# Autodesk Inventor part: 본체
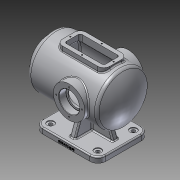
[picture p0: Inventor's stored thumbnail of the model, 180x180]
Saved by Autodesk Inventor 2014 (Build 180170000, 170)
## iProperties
Created: 2021-11
Part Number: 본체
Material: 알루미늄 6061
Document SubType Name: Modeling
Designer: kb542-04
Density: 2.71 g/cm^3
Appearance: 알루미늄 - 평지
Mass: 3554.85 g
Surface Area: 2408.31 cm^2
Volume: 1311.75 cm^3
Author: kb542-04
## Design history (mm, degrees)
sketch "스케치1"
  geometry: L1 (0, 0)-(210, 0); L2 (0, 32.5)-(25, 32.5); L3 (25, 32.5)-(25, 55); L4 (25, 55)-(181.239, 55); L5 (0, 32.5)-(0, 47.5); L6 (0, 47.5)-(10, 47.5); L7 (10, 47.5)-(10, 65); L8 (10, 65)-(181.239, 65); L9 (0, 101.95)-(170, 101.95); L10 (210, 0)-(210, 59.358); A1 r 100 centre (110, 0) between (210, 0) and (189.154, 61.111); A2 r 90 centre (110, 0) between (200, 0) and (181.239, 55); A3 r 10 centre (181.239, 55) between (189.154, 61.111) and (181.239, 65); 1 further point
  constraints: 20 end point, 7 point on circle, 5 parallel, 4 perpendicular, 3 centre point, 3 tangent, 2 point on line, 2 vertical alignment, 1 concentric, 1 horizontal
  dimensions: "d1" = 210 distance of L1.start L1.end; "d2" = 10 radial gap between concentric circles of A1 A2; "d3" = 25 distance of L2.start L2.end; "d4" = 65 diameter of L2 L1; "d5" = 95 diameter of L6 L1; "d6" = 130 diameter of L8 L1; "d7" = 10 distance between parallel lines of L7 L5; "d8" = 110 diameter of L4 L1; "d30" = 100 radius of A1; "d31" = 170 distance of L9.start L9.end; "d32" = 10 radius of A3
revolve "회전1" sketch "스케치1" stored, may be unused: angle "d10" = 90 deg
node "작업 평면1"
sketch "스케치2"
  geometry: L1 (50, -30)-(170, -30); L2 (170, -30)-(170, 30); L3 (170, 30)-(50, 30); L4 (50, 30)-(50, -30); L5 (60, -20)-(160, -20); L6 (160, -20)-(160, 20); L7 (160, 20)-(60, 20); L8 (60, 20)-(60, -20); 2 further points
  constraints: 16 end point, 4 parallel, 2 horizontal, 2 perpendicular, 1 horizontal alignment, 1 midpoint
  dimensions: "d12" = 120 distance of L2.end L3.end; "d13" = 10 distance between parallel lines of L7 L3; "d14" = 10 distance between parallel lines of L2 L6; "d15" = 10 distance between parallel lines of L4 L8; "d16" = 10 distance between parallel lines of L1 L5; "d17" = 50 distance from line of L4 point (0, 0); "d18" = 60 distance of L3.end L1.start
extrude "돌출1" join sketch "스케치2" stored distance "d19" = 10; taper "d20" = 0 deg
sketch "스케치3"
  geometry: L1 (170, 30)-(50, 30) reference; L2 (50, 30)-(50, -30) reference; L3 (50, -30)-(170, -30) reference; L4 (170, -30)-(170, 30) reference; L5 (55, 25)-(165, 25); L6 (165, 25)-(165, -25); L7 (165, -25)-(55, -25); L8 (55, -25)-(55, 25); 5 further points
  constraints: 8 end point, 4 midpoint, 3 other
  dimensions: "d21" = 50 distance of L7.end L5.start; "d22" = 55 horizontal distance of point (110, 25) point (55, 0) (derived)
hole "구멍1" sketch "스케치3" at (110, 25), (55, 0), (165, 0), (110, -25) diameter "d23" = 3.242; stored, may be unused: countersink angle "d27" = 90 deg, drill point angle "d29" = 118 deg; dims "d24" = 9, "d25" = 4, "d26" = 2, "d28" = 11
node "작업 평면2"
sketch "스케치4"
  geometry: L1 (30, 65)-(190, 65); L2 (190, 65)-(190, -65); L3 (190, -65)-(30, -65); L4 (30, -65)-(30, 65); L5 (0, -47.5)-(0, 47.5) reference; 2 further points
  constraints: 8 end point, 2 parallel, 1 horizontal, 1 horizontal alignment, 1 midpoint, 1 perpendicular
  dimensions: "d34" = 160 distance of L1.start L1.end; "d35" = 130 distance of L3.end L1.start; "d36" = 30 distance between parallel lines of L4 L5
extrude "돌출2" join sketch "스케치4" distance "d37" = 14; taper "d38" = 0 deg
fillet "모깎기1" dims "d39" = 20
sketch "스케치5"
  geometry: L1 (170, 7)-(170, -7); L2 (50, -7)-(50, 7); L3 (103, 50)-(117, 50); L4 (117, -50)-(103, -50); L5 (50, 7)-(103, 7); L6 (117, 7)-(170, 7); L7 (103, -50)-(103, -7); L8 (103, 7)-(103, 50); L9 (170, -7)-(117, -7); L10 (103, -7)-(50, -7); L11 (117, 50)-(117, 7); L12 (117, -7)-(117, -50); L13 (30, -45)-(30, 45) reference; 2 further points
  constraints: 24 end point, 10 parallel, 6 collinear, 4 perpendicular, 3 horizontal, 1 horizontal alignment, 1 midpoint
  dimensions: "d40" = 14 distance of L3.start L3.end; "d41" = 14 distance of L1.start L1.end; "d42" = 73 distance between parallel lines of L8 L13; "d43" = 120 distance between parallel lines of L1 L2; "d44" = 100 distance between parallel lines of L3 L4
extrude "돌출3" join sketch "스케치5" stored distance "d45" = 14; taper "d46" = 0 deg
feature "면 기울기1" dims angle "d47" = 20 deg
feature "면 기울기2" dims angle "d48" = 20 deg
feature "면 기울기3" dims angle "d49" = 20 deg
feature "면 기울기4" dims angle "d50" = 20 deg
node "작업 평면3"
sketch "스케치6"
  geometry: C1 r 40 at (-127, 0); 1 further point
  constraints: 1 centre point, 1 horizontal alignment
  dimensions: "d52" = 80 diameter of C1; "d53" = 127 distance of C1.centre point (0, 0)
extrude "돌출4" join sketch "스케치6" stored distance "d54" = 14; taper "d55" = 0 deg
hole "구멍2" diameter "d58" = 42; stored, may be unused: countersink angle "d62" = 90 deg, drill point angle "d64" = 118 deg; dims "d56" = 10, "d57" = 10, "d59" = 9, "d60" = 52, "d61" = 18, "d63" = 11
extrude "돌출5" cut sketch "스케치2" stored distance "d65" = 14; taper "d66" = 0 deg
sketch "스케치7"
  geometry: C1 r 40 at (0, 0) reference; A1 r 32.5 centre (0, 0) between (0, -32.5) and (-32.5, 0); 3 further points
  constraints: 4 point on circle, 2 horizontal alignment, 2 vertical alignment, 1 centre point, 1 coincident
  dimensions: "d67" = 65 diameter of A1
hole "구멍3" sketch "스케치7" at (0, -32.5), (-32.5, 0), (0, 32.5), (32.5, 0) diameter "d68" = 3.242; stored, may be unused: countersink angle "d72" = 90 deg, drill point angle "d74" = 118 deg; dims "d69" = 11, "d70" = 52, "d71" = 18, "d73" = 13
hole "구멍4" diameter "d77" = 9; stored, may be unused: countersink angle "d81" = 90 deg, drill point angle "d83" = 118 deg; dims "d75" = 10, "d76" = 10, "d78" = 11, "d79" = 18, "d80" = 2, "d82" = 13
hole "구멍5" diameter "d86" = 9; stored, may be unused: countersink angle "d90" = 90 deg, drill point angle "d92" = 118 deg; dims "d84" = 10, "d85" = 10, "d87" = 11, "d88" = 18, "d89" = 2, "d91" = 13
hole "구멍6" diameter "d95" = 9; stored, may be unused: countersink angle "d99" = 90 deg, drill point angle "d101" = 118 deg; dims "d93" = 10, "d94" = 10, "d96" = 11, "d97" = 18, "d98" = 2, "d100" = 13
hole "구멍7" diameter "d104" = 9; stored, may be unused: countersink angle "d108" = 90 deg, drill point angle "d110" = 118 deg; dims "d102" = 10, "d103" = 10, "d105" = 11, "d106" = 18, "d107" = 2, "d109" = 13
fillet "모깎기2" dims "d111" = 3, "d112" = 15, "d113" = 5
fillet "모깎기3" dims "d114" = 3
node "작업 평면5"
sketch "스케치8"
  geometry: L1 (0, 11)-(120, 11) reference; L2 (120, 0)-(0, 0) reference; 3 further points
  constraints: 1 midpoint, 1 vertical alignment, 1 other
  dimensions: "d116" = 5 distance from line of point (60, 5) L2
feature "엠보싱1" sketch "스케치8" dims "d12" = 120, "d13" = 10, "d14" = 10, "d15" = 10, "d16" = 10, "d17" = 50, "d18" = 60, "d117" = 0.5, "d118" = 0
chamfer "모따기1" distance "d119" = 1; stored, may be unused: second distance "d120" = 2, angle "d121" = 45 deg
fillet "모깎기4" dims "d122" = 10, "d123" = 3
sketch "스케치9"
  geometry: A1 r 40 centre (0, 0) between (40, 0) and (0, -40); 3 further points
  constraints: 4 point on circle, 2 horizontal alignment, 2 vertical alignment, 1 centre point, 1 coincident
  dimensions: "d124" = 80 diameter of A1
hole "구멍8" sketch "스케치9" at (40, 0), (0, -40), (0, 40), (-40, 0) diameter "d125" = 3.242; stored, may be unused: countersink angle "d129" = 90 deg, drill point angle "d131" = 118 deg; dims "d126" = 11, "d127" = 18, "d128" = 2, "d130" = 13
chamfer "모따기2" distance "d132" = 1; stored, may be unused: second distance "d133" = 2, angle "d134" = 45 deg
fillet "모깎기5" dims "d135" = 0.3
fillet "모깎기6" dims "d136" = 3
node "솔리드1"
mirror "대칭1"
node "작업 평면4"
other parameters: "d33" = -114, "d51" = 75, "d115" = 239.5
